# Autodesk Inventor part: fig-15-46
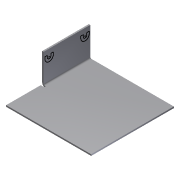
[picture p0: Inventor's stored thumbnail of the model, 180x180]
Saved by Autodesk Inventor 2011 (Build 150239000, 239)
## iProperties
Created: 2005-03
Part Number: fig-15-46
Document SubType Name: Sheet Metal
Designer: CADCIM
Manufacturer: Standard
Standards Organization: Custom
Density: 1 g/cm^3
Sheet Metal Rule: Default
Author: CADCIM
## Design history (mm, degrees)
node "Face1"
  sketch "Sketch1"
    geometry: L1 (-29, -26)-(30, -26); L2 (30, -26)-(30, 31.375); L3 (30, 31.375)-(-29, 31.375); L4 (-29, 31.375)-(-29, -26)
    constraints: 8 end point, 2 parallel, 1 horizontal, 1 perpendicular
node "Flange1"
sketch "Sketch4"
  geometry: L1 (3.278, 0.812)-(4.721, 0.812); L2 (4.721, 6.681)-(3.278, 6.681); L3 (3.278, 4.946)-(4.721, 4.946); L4 (4.721, 2.546)-(3.278, 2.546); L5 (3.278, 0.812)-(3.278, 2.546); L6 (3.278, 4.946)-(3.278, 6.681); L7 (3.278, 31.563)-(4.721, 31.563); L8 (4.721, 25.694)-(3.278, 25.694); L9 (3.278, 27.429)-(4.721, 27.429); L10 (4.721, 29.829)-(3.278, 29.829); L11 (3.278, 31.563)-(3.278, 29.829); L12 (3.278, 27.429)-(3.278, 25.694); A1 r 2.935 centre (4.721, 3.746) between (4.721, 0.812) and (4.721, 6.681); A2 r 1.2 centre (4.721, 3.746) between (4.721, 2.546) and (4.721, 4.946); A3 r 2.935 centre (4.721, 28.629) between (4.721, 25.694) and (4.721, 31.563); A4 r 1.2 centre (4.721, 28.629) between (4.721, 27.429) and (4.721, 29.829)
  constraints: 24 end point, 8 point on circle, 4 centre point, 3 equal length, 2 tangent, 1 horizontal, 1 perpendicular, 1 vertical alignment, 2 other
body "Solid1"
face "Plate1" dims "Thickness" = 1
sketch "Sketch2"
  geometry: L1 (25, 0)-(57.375, 0); L2 (57.375, 0)-(57.375, 20); L3 (57.375, 20)-(25, 20); L4 (25, 20)-(25, 0)
  constraints: 8 end point
face "Plate2" dims "d1" = 0, "d2" = 25, "d3" = 1 (= BendReliefWidth), "d5" = 2 (= MinimumRemnant), "d7" = 20, "d8" = 90 deg, "d9" = 1 (= BendRadius), "Thickness" = 1
bend "Bend1" dims "d3" = 1 (= BendReliefWidth), "d4" = 0.5 (= BendReliefDepth), "d5" = 2 (= MinimumRemnant), "d6" = 1 (= BendRadius), "d7" = 20, "d8" = 90 deg, "d9" = 1 (= BendRadius), "SeamGap" = 0.01, "Thickness" = 1
other parameters: "BendRadius" = 1 (= Thickness), "BendReliefWidth" = 1 (= Thickness), "BendReliefDepth" = 0.5 (= 0.5 x Thickness), "CornerReliefSize" = 4 (= 4 x Thickness), "MinimumRemnant" = 2 (= 2 x Thickness), "TransitionRadius" = 1 (= BendRadius), "d0" = 1 (= BendRadius), "JacobiRadiusSize" = 1 (= Thickness), "GapSize" = 1 (= Thickness)
